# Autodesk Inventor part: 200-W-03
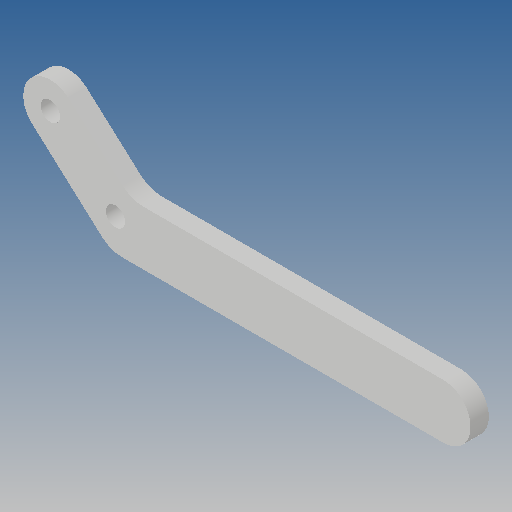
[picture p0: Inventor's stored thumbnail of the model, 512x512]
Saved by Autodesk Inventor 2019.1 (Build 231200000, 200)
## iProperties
Created: 2011-05
Part Number: 200-W-03
Material: Ogólny
Document SubType Name: Modeling
Designer: CADENGINEERING4
Density: 1 g/cm^3
Appearance: Domyślna
Author: CADENGINEERING4
Revision Number: ÈÎºÎ
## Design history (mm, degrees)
feature "À­Éì1"
node "Bryła1"
